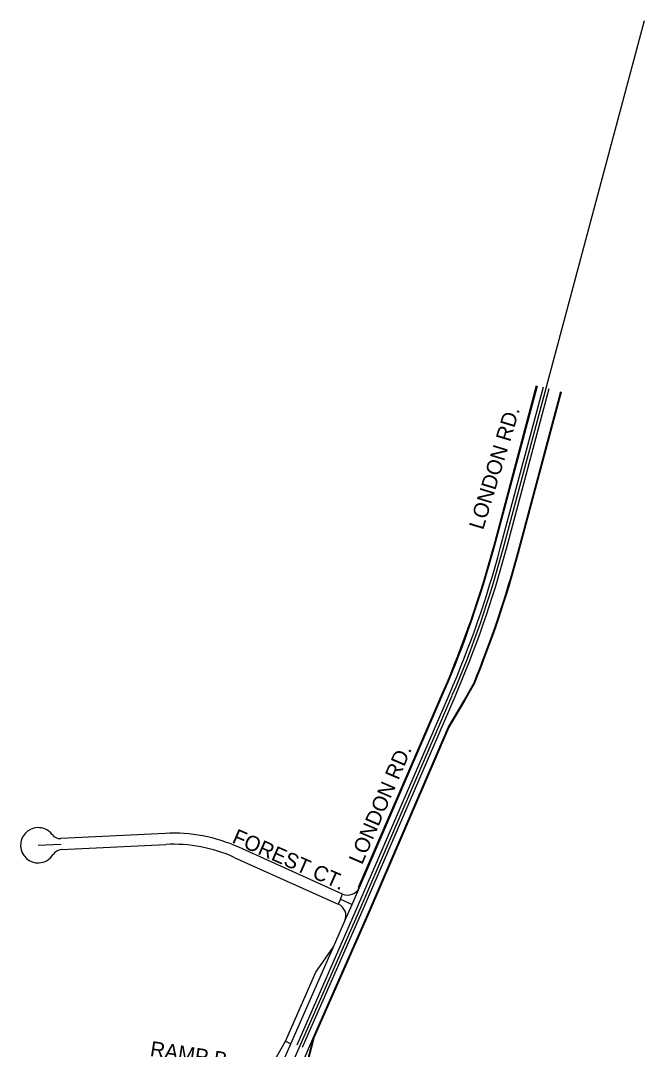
# Model space of a CAD drawing. Extents: x 2315515 to 2326910, y 758186 to 762794.
# Drawn here: x 2320679 to 2321918, y 760752 to 762794 of the extents above; entities that cross this region are included whole.
import ezdxf

# ---------------------------------------------------------------- set-up
doc = ezdxf.new("R2010")
doc.units = 0
for name, color, linetype in [('Default', 7, 'Continuous'), ('Draft_Corr_Final', 7, 'Continuous'), ('Pavement Marking Yellow', 7, 'Continuous'), ('Road_Curb_Face', 7, 'Continuous'), ('TL_Base Extension Sub', 7, 'Continuous'), ('TL_End Condition Ditch Out', 7, 'Continuous'), ('TL_End Condition Hinge', 7, 'Continuous'), ('TL_Pavement Edge', 7, 'Continuous')]:
    doc.layers.add(name, color=color, linetype=linetype)

msp = doc.modelspace()

# ---------------------------------------------------------------- linework, layer by layer
at = {"layer": 'Default'}
for p, q in [((2321637, 761745.2), (2321917.6, 762793.6)), ((2321637, 761745.2), (2321917.6, 762793.6)), ((2321637, 761745.2), (2321917.6, 762793.6)), ((2321353.4, 761032.3), (2321535.9, 761454.5)), ((2321353.4, 761032.3), (2321535.9, 761454.5)), ((2321353.4, 761032.3), (2321535.9, 761454.5)), ((2320896.6, 759992.2), (2321353.4, 761032.3)), ((2320896.6, 759992.2), (2321353.4, 761032.3)), ((2320896.6, 759992.2), (2321353.4, 761032.3))]:
    msp.add_line(p, q, dxfattribs=at)
msp.add_arc((2319608.4, 762288), 2100, 336.617, 345.0204, dxfattribs=at)
msp.add_arc((2319608.4, 762288), 2100, 336.617, 345.0204, dxfattribs=at)
msp.add_arc((2319608.4, 762288), 2100, 336.617, 345.0204, dxfattribs=at)
msp.add_open_spline([(2321559.3, 761444.4), (2321559.6, 761445), (2321560.3, 761446.1), (2321561.2, 761447.8), (2321562.2, 761449.5), (2321563.2, 761451.2), (2321564.1, 761452.9), (2321565.1, 761454.5), (2321566.1, 761456.2), (2321567, 761457.9), (2321568, 761459.6), (2321569, 761461.3), (2321569.9, 761463), (2321570.9, 761464.7), (2321571.8, 761466.4), (2321572.8, 761468.1), (2321573.7, 761469.7), (2321574.7, 761471.4), (2321575.6, 761473.1), (2321576.6, 761474.8), (2321577.5, 761476.5), (2321578.2, 761477.7), (2321578.5, 761478.2)], degree=3, dxfattribs=at)
at = {"layer": 'Draft_Corr_Final'}
for p, q in [((2321619.7, 761749.8), (2321705, 762068.7)), ((2321619.7, 761749.8), (2321705, 762068.7)), ((2321666, 761737.4), (2321751.6, 762057.4)), ((2321666, 761737.4), (2321751.6, 762057.4)), ((2321351.4, 761073.1), (2321519.4, 761461.7)), ((2321351.4, 761073.1), (2321519.4, 761461.7)), ((2321527.9, 761390.6), (2321559.3, 761444.4)), ((2321527.9, 761390.6), (2321559.3, 761444.4)), ((2321369.9, 761025.1), (2321527.9, 761390.6)), ((2321369.9, 761025.1), (2321527.9, 761390.6)), ((2320965.7, 761180.6), (2320758.4, 761170.3)), ((2320965.7, 761180.6), (2320758.4, 761170.3)), ((2320759.5, 761148.3), (2320966.8, 761158.6)), ((2321318.2, 761060.2), (2321112, 761153)), ((2321318.2, 761060.2), (2321112, 761153)), ((2321102.9, 761132.9), (2321309.2, 761040.1)), ((2321313.7, 761050.2), (2321318.2, 761060.2)), ((2321313.7, 761050.2), (2321309.2, 761040.1)), ((2321309.9, 761039.8), (2321309.2, 761040.1)), ((2321261, 760777.3), (2321369.9, 761025.1)), ((2321261, 760777.3), (2321369.9, 761025.1)), ((2321299.9, 760955.4), (2321322.6, 761006.9)), ((2321299.9, 760955.4), (2321322.6, 761006.9)), ((2321264.8, 760905.3), (2321299.9, 760955.4)), ((2321204.5, 760767.9), (2321264.8, 760905.3)), ((2321207.9, 760775.6), (2321264.8, 760905.3)), ((2321248.3, 760728.3), (2321261, 760777.3)), ((2321184.8, 760732.9), (2321204.5, 760767.9))]:
    msp.add_line(p, q, dxfattribs=at)
for centre, radius, start, end in [((2319608.4, 762288), 2082, 336.617, 345.0204), ((2319608.4, 762288), 2082, 336.617, 345.0204), ((2319608.4, 762288), 2130, 337.6565, 345.0204), ((2319608.4, 762288), 2130, 337.6565, 345.0204), ((2320713.6, 761157), 35, 92.8425, 272.8425), ((2320713.6, 761157), 35, 37.1502, 92.8425), ((2320757.4, 761190.2), 20, 217.1502, 272.8425), ((2320757.4, 761190.2), 20, 217.1502, 272.8425), ((2320981.5, 760863), 318, 65.781, 92.8425), ((2320981.5, 760863), 318, 65.781, 92.8425), ((2320760.5, 761128.3), 20, 92.8425, 148.5349), ((2320760.5, 761128.3), 20, 92.8425, 148.5349), ((2320981.5, 760863), 296, 65.781, 92.8425), ((2320713.6, 761157), 35, 272.8425, 328.5349), ((2321328.4, 761083), 25, 245.781, 336.617), ((2321299.7, 761017), 25, 336.2923, 65.781), ((2321299.7, 761017), 25, 336.2923, 65.781)]:
    msp.add_arc(centre, radius, start, end, dxfattribs=at)
msp.add_open_spline([(2321559.3, 761444.4), (2321559.6, 761445), (2321560.3, 761446.1), (2321561.2, 761447.8), (2321562.2, 761449.5), (2321563.2, 761451.2), (2321564.1, 761452.9), (2321565.1, 761454.5), (2321566.1, 761456.2), (2321567, 761457.9), (2321568, 761459.6), (2321569, 761461.3), (2321569.9, 761463), (2321570.9, 761464.7), (2321571.8, 761466.4), (2321572.8, 761468.1), (2321573.7, 761469.7), (2321574.7, 761471.4), (2321575.6, 761473.1), (2321576.6, 761474.8), (2321577.5, 761476.5), (2321578.2, 761477.7), (2321578.5, 761478.2)], degree=3, dxfattribs=at)
at = {"layer": 'Pavement Marking Yellow'}
for p, q in [((2321631.2, 761746.7), (2321716.9, 762066.7)), ((2321642.8, 761743.6), (2321728.5, 762063.6)), ((2321347.9, 761034.7), (2321530.4, 761456.9)), ((2321358.9, 761029.9), (2321541.4, 761452.2)), ((2321227.8, 760761.2), (2321347.9, 761034.7)), ((2321238.8, 760756.5), (2321358.9, 761029.9))]:
    msp.add_line(p, q, dxfattribs=at)
for radius in [2094, 2106]:
    msp.add_arc((2319608.4, 762288), radius, 336.617, 345.0204, dxfattribs=at)
at = {"layer": 'Road_Curb_Face'}
for p, q in [((2321618.2, 761750.2), (2321703.5, 762069.1)), ((2321667.5, 761737), (2321753.1, 762057)), ((2321667.5, 761737), (2321753.1, 762057)), ((2321579.8, 761477.5), (2321579.8, 761477.6)), ((2321350, 761073.7), (2321518, 761462.3)), ((2321529.2, 761389.8), (2321560.6, 761443.7)), ((2321529.2, 761389.9), (2321560.6, 761443.7)), ((2321371.3, 761024.5), (2321529.3, 761390)), ((2321371.3, 761024.5), (2321529.2, 761389.9)), ((2321262.4, 760776.7), (2321371.3, 761024.5)), ((2321262.5, 760776.8), (2321371.3, 761024.5)), ((2321249.7, 760727.9), (2321262.5, 760776.9)), ((2321249.7, 760727.9), (2321262.5, 760776.8))]:
    msp.add_line(p, q, dxfattribs=at)
for radius, start in [(2080.5, 336.617), (2131.5, 337.6542), (2131.5, 337.6565)]:
    msp.add_arc((2319608.4, 762288), radius, start, 345.0204, dxfattribs=at)
msp.add_open_spline([(2321560.6, 761443.7), (2321560.8, 761444), (2321561.4, 761445.1), (2321562.6, 761447.1), (2321563.5, 761448.7), (2321564.5, 761450.4), (2321565.4, 761452.1), (2321566.4, 761453.8), (2321567.4, 761455.5), (2321568.3, 761457.2), (2321569.3, 761458.9), (2321570.3, 761460.6), (2321571.2, 761462.2), (2321572.2, 761463.9), (2321573.1, 761465.6), (2321574.1, 761467.3), (2321575.1, 761469), (2321576, 761470.7), (2321577, 761472.4), (2321577.9, 761474), (2321579, 761476.1), (2321579.6, 761477.2), (2321579.8, 761477.5)], degree=2, dxfattribs=at)
msp.add_open_spline([(2321560.6, 761443.7), (2321560.8, 761444), (2321561.4, 761445.1), (2321562.6, 761447.1), (2321563.5, 761448.7), (2321564.5, 761450.4), (2321565.4, 761452.1), (2321566.4, 761453.8), (2321567.4, 761455.5), (2321568.3, 761457.2), (2321569.3, 761458.9), (2321570.3, 761460.6), (2321571.2, 761462.2), (2321572.2, 761463.9), (2321573.1, 761465.6), (2321574.1, 761467.3), (2321575.1, 761469), (2321576, 761470.7), (2321577, 761472.4), (2321577.9, 761474), (2321579, 761476.1), (2321579.6, 761477.2), (2321579.8, 761477.5)], degree=2, dxfattribs=at)
at = {"layer": 'TL_Base Extension Sub'}
msp.add_line((2321215.5, 760763.1), (2321299.9, 760955.4), dxfattribs=at)
at = {"layer": 'TL_End Condition Ditch Out'}
for p, q in [((2321336.9, 761039.5), (2321351.4, 761073.1)), ((2321313.7, 761050.2), (2321337, 761039.7)), ((2321322.6, 761006.9), (2321336.9, 761039.5)), ((2321196.2, 760629.7), (2321261, 760777.3)), ((2321163, 760643.5), (2321215.5, 760763.1)), ((2321204.5, 760767.9), (2321215.5, 760763.1))]:
    msp.add_line(p, q, dxfattribs=at)
at = {"layer": 'TL_End Condition Hinge'}
msp.add_line((2320713.6, 761157), (2320759, 761159.3), dxfattribs=at)
at = {"layer": 'TL_Pavement Edge'}
for radius in [0.0594, 0.0061, 0.00167, 0.00113]:
    msp.add_circle((2320713.6, 761157), radius, dxfattribs=at)

# ---------------------------------------------------------------- texts
at = {"layer": 'Default'}
for s, rotation, p in [('LONDON RD.', 73.0343, (2321597.1, 761781.4)), ('LONDON RD.', 66.7465, (2321356.7, 761117)), ('FOREST CT.', 336.3217, (2321096.7, 761163)), ('RAMP B', 351.3639, (2320934.5, 760739))]:
    msp.add_text(s, height=30, rotation=rotation, dxfattribs=at).set_placement(p)

doc.saveas('drawing.dxf')
